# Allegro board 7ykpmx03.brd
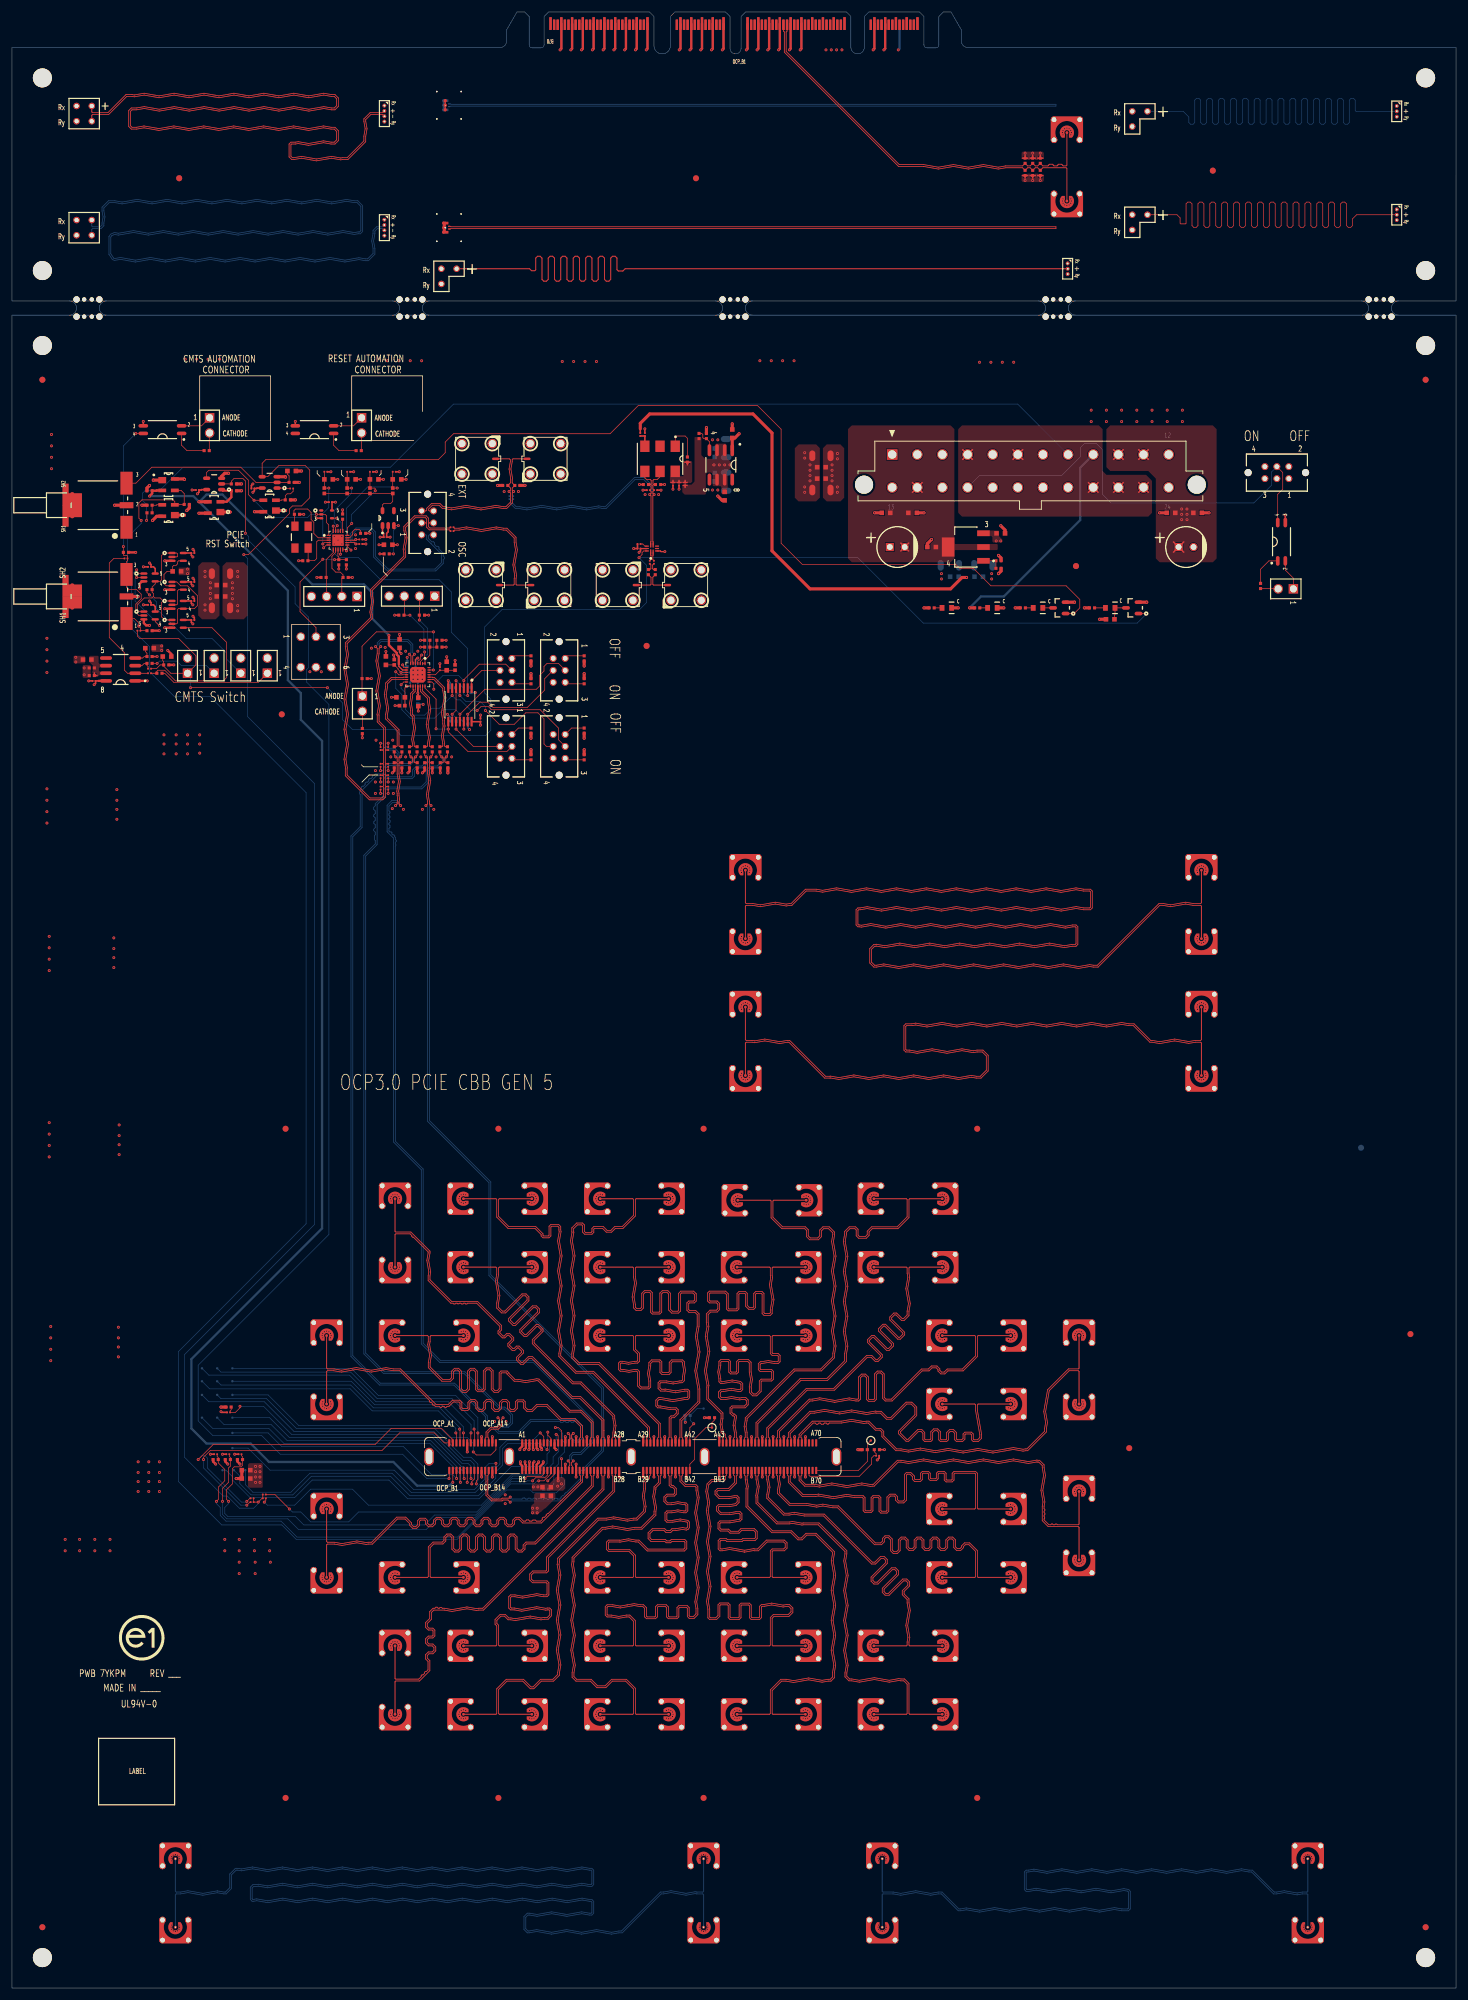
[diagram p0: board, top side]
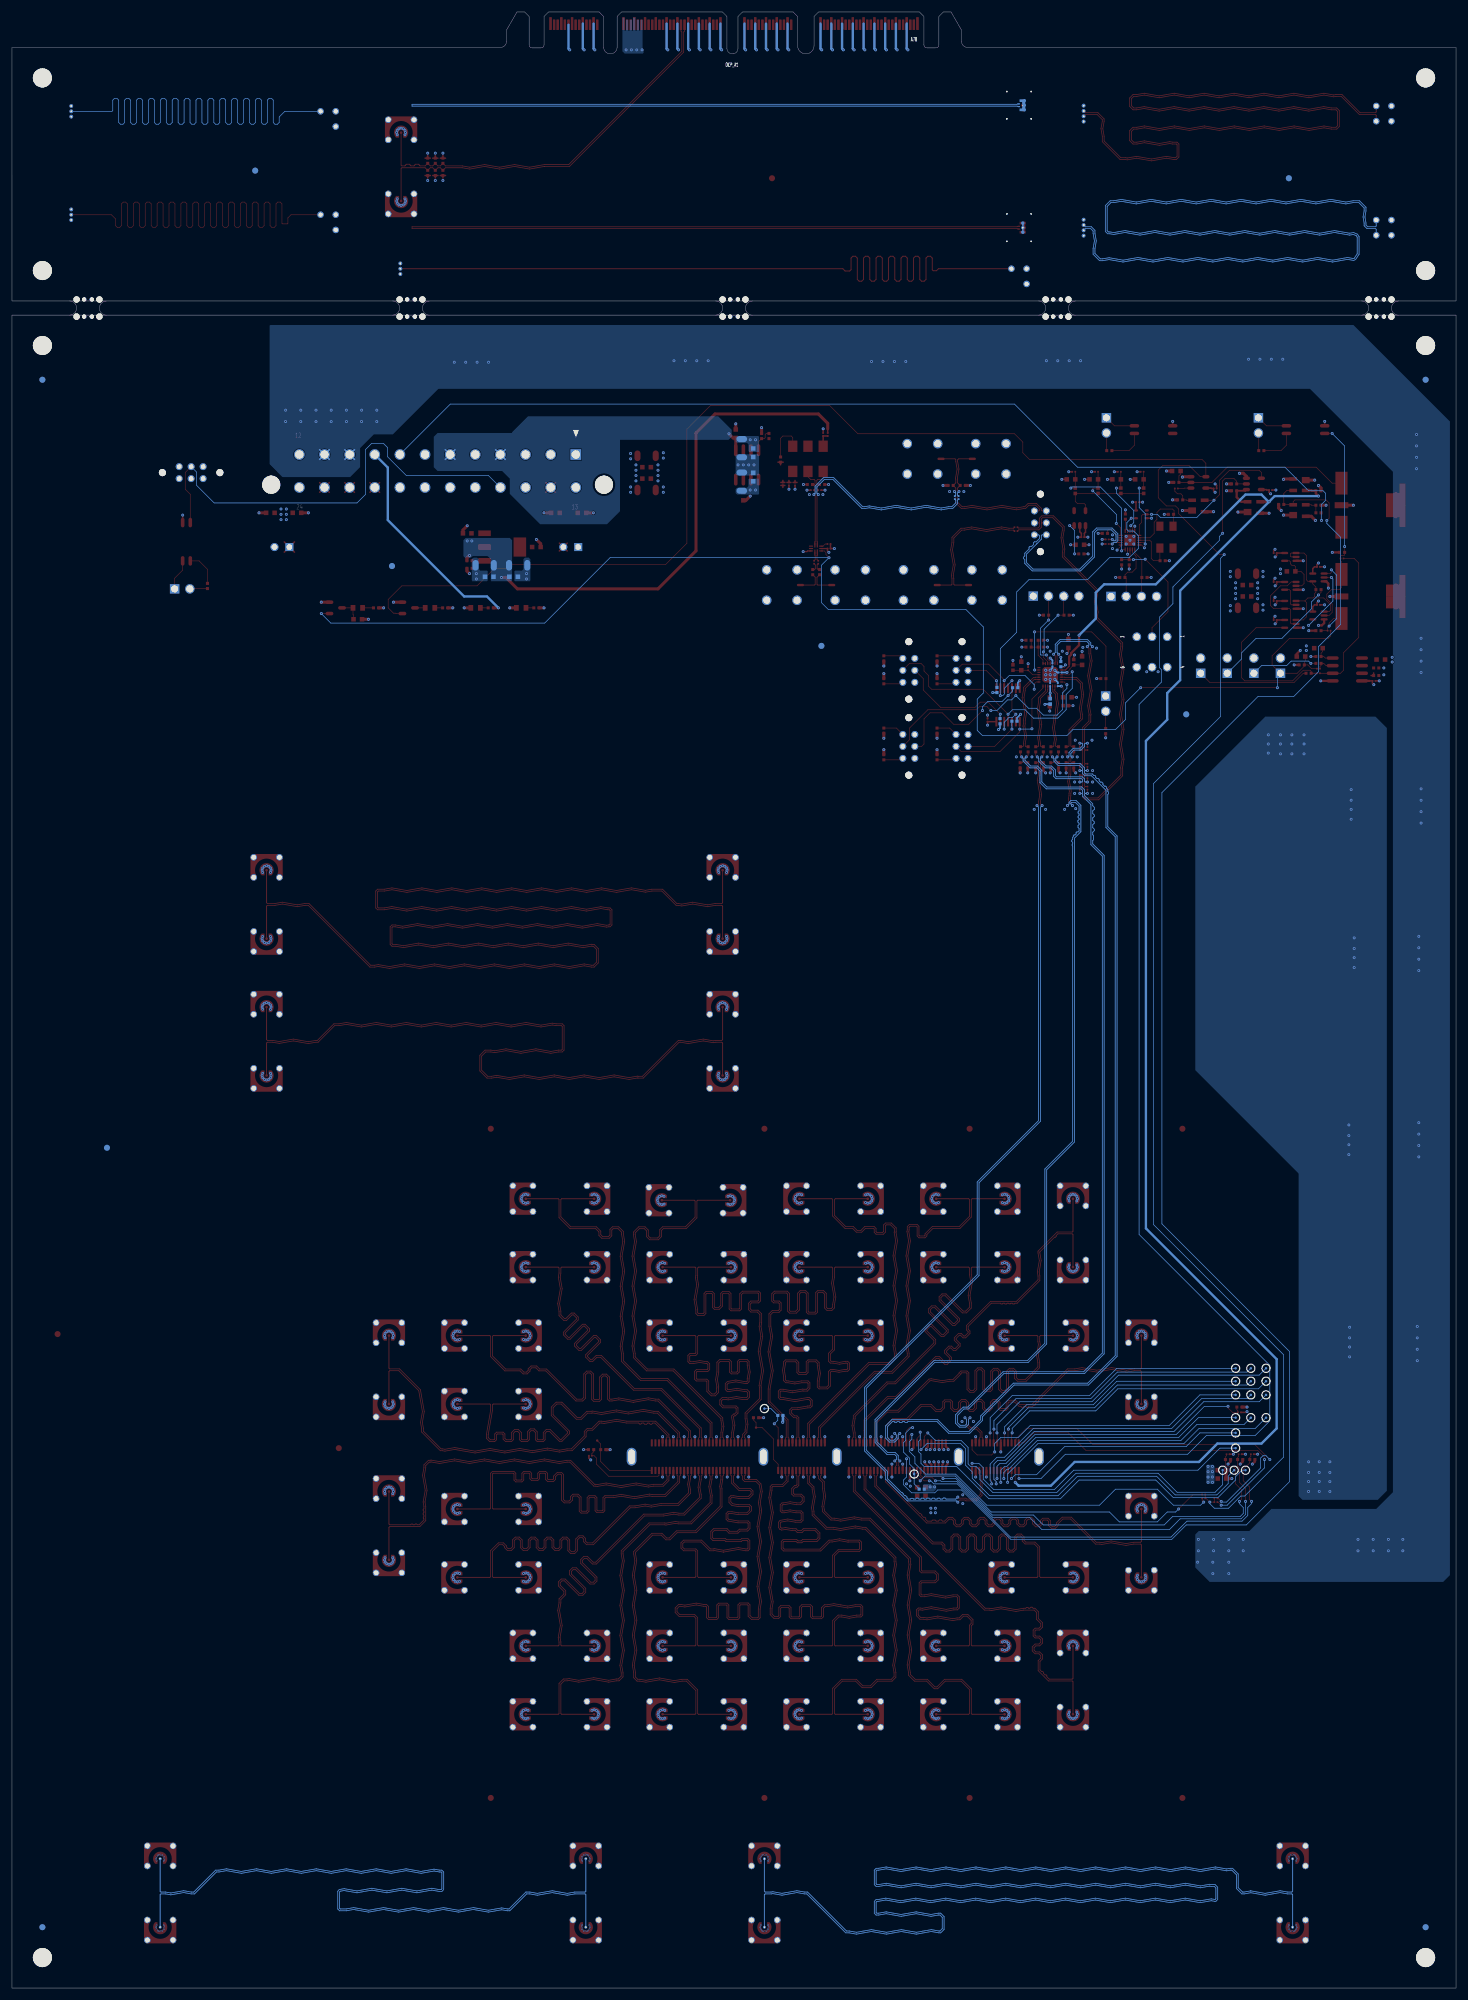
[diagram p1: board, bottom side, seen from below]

Outline 241.3 x 330.03 mm; copper layers: TOP, GND, VCC, GD2, GD3, BOTTOM. Coordinates in mm from the lower left corner of the outline.
Outline path: 9.62,281.75 arc(10.79,280.57) 9.62,279.39 ; 15.77,279.4 arc(14.6,280.58) 15.77,281.76 ; 63.6,281.75 arc(64.77,280.57) 63.6,279.39 ; 69.75,279.4 arc(68.58,280.58) 69.75,281.76 ; 117.57,281.75 arc(118.74,280.57) 117.57,279.39 ; 123.72,279.4 arc(122.55,280.58) 123.72,281.76 ; 171.55,281.75 arc(172.72,280.57) 171.55,279.39 ; 177.7,279.4 arc(176.53,280.58) 177.7,281.76 ; 225.52,281.75 arc(226.69,280.57) 225.52,279.39 ; 231.67,279.4 arc(230.5,280.58) 231.67,281.76 ; 0,324.1 0,281.76 241.3,281.76 241.3,324.1 159.72,324.1 arc(158.96,324.41) 158.65,325.16 158.65,327.03 156.92,330.03 155.64,330.03 154.89,329.28 154.89,324.53 arc(154.74,324.17) 154.39,324.03 152.89,324.03 arc(152.54,324.17) 152.39,324.53 152.39,329.28 151.64,330.03 143.18,330.03 142.43,329.28 142.43,324.15 arc(141.31,323.03) 140.18,324.15 140.18,329.28 139.43,330.03 122.58,330.03 121.83,329.28 121.83,323.95 arc(120.91,323.03) 119.98,323.95 119.98,329.28 119.23,330.03 110.77,330.03 110.02,329.28 110.02,324.4 arc(108.65,323.03) 107.27,324.4 107.27,329.28 106.52,330.03 89.66,330.03 88.91,329.28 88.91,324.53 arc(88.77,324.17) 88.41,324.03 86.91,324.03 arc(86.56,324.17) 86.41,324.53 86.41,329.28 85.66,330.03 84.38,330.03 82.65,327.03 82.65,325.16 arc(82.34,324.41) 81.58,324.1 0,324.1 ; 0,279.4 241.3,279.4 241.3,0 0,0 0,279.4

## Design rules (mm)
constraint set DEFAULT: min track width 0.102
net group ATX_PWR_OK_33: nets ATX_PWR_OK ATX_PWR_OK_33
net group CLK_EXTERNAL_DN: nets CLK_EXTERNAL_DN CLK_OSC1_TO_TRIGGER_DN
net group CLK_EXTERNAL_DP: nets CLK_EXTERNAL_DP CLK_OSC1_TO_TRIGGER_DP
net group CLKBUF_EN_DLY: nets CLKBUF_EN_DLY N16884462
net group N16775589: nets N16775589 N16775601
net group REFCLK0_R: nets REFCLK0_R_DN REFCLK0_R_DP
net group REFCLK1_R: nets REFCLK1_R_DN REFCLK1_R_DP
net group REFCLK2_R: nets REFCLK2_R_DN REFCLK2_R_DP
net group REFCLK3_R: nets REFCLK3_R_DN REFCLK3_R_DP
net group SET2DIL: nets SET2DIL_85_BOT SET2DIL_85_TOP
net group V_5VSTBY: nets N16831963 V_5VSTBY
net group 555_OUT: nets 555_OUT 555_OUT_JP BTN_NC BUS_SEL
net group 555_TRI: nets 555_TRI N16776527 N16776623
net group _UNCONSTRAINED: nets 555_DISCHARGE AUX_PWR_EN BIF0_N BIF1_N BIF2_N CLKBUF_OE0_OFF CLKBUF_OE0_ON CLKBUF_OE1_OFF CLKBUF_OE1_ON CLKBUF_OE2_OFF CLKBUF_OE2_ON CLKBUF_OE3_OFF CLKBUF_OE3_ON NCSI_ARBIN NCSI_ARBOUT NCSI_CRS_DV NCSI_TXEN SCAN_DATA_IN SCAN_DATA_OUT SCAN_LD_N SLOT_ID
net group CLK_SE: nets 555_RST_N CLK_NCSI NCSI_RXD0 NCSI_RXD1 NCSI_TXD0 NCSI_TXD1 NIC_PWR_GOOD SCAN_CLK SMB_CLK SMB_RST_N SMB_SDA WAKE_N
net group CLK_TRIG_SIGNAL_C_DN: nets CLK_TRIG_SIGNAL_C_DN CLK_TRIG_SIGNAL_DN CLK_TRIG_SIGNAL_R_DN
net group CLK_TRIG_SIGNAL_C_DP: nets CLK_TRIG_SIGNAL_C_DP CLK_TRIG_SIGNAL_DP CLK_TRIG_SIGNAL_R_DP
net group COUPONS: nets Z_85D_BOT_DN Z_85D_BOT_DP Z_85D_TOP_DN Z_85D_TOP_DP
net group GND: nets GND_SIGNAL
net group GND_OSC1: nets 337_ADJ GND_OSC1 V_1P65_NEG
net group PE_SIGNALS: nets PE_CAL_CPU_OCP_0_DN PE_CAL_CPU_OCP_0_DP PE_CPU_OCP_0_DN PE_CPU_OCP_0_DP PE_CPU_OCP_1_DN PE_CPU_OCP_1_DP PE_CPU_OCP_2_DN PE_CPU_OCP_2_DP PE_CPU_OCP_3_DN PE_CPU_OCP_3_DP PE_CPU_OCP_4_DN PE_CPU_OCP_4_DP PE_CPU_OCP_5_DN PE_CPU_OCP_5_DP PE_CPU_OCP_6_DN PE_CPU_OCP_6_DP PE_CPU_OCP_7_DN PE_CPU_OCP_7_DP PE_CPU_OCP_8_DN PE_CPU_OCP_8_DP PE_CPU_OCP_9_DN PE_CPU_OCP_9_DP PE_CPU_OCP_10_DN PE_CPU_OCP_10_DP PE_CPU_OCP_11_DN PE_CPU_OCP_11_DP PE_CPU_OCP_12_DN PE_CPU_OCP_12_DP PE_CPU_OCP_13_DN PE_CPU_OCP_13_DP PE_CPU_OCP_14_DN PE_CPU_OCP_14_DP PE_CPU_OCP_15_DN PE_CPU_OCP_15_DP PE_OCP_CPU_0_DN PE_OCP_CPU_0_DP PE_OCP_CPU_1_DN PE_OCP_CPU_1_DP PE_OCP_CPU_2_DN PE_OCP_CPU_2_DP PE_OCP_CPU_3_DN PE_OCP_CPU_3_DP PE_OCP_CPU_4_DN PE_OCP_CPU_4_DP PE_OCP_CPU_5_DN PE_OCP_CPU_5_DP PE_OCP_CPU_6_DN PE_OCP_CPU_6_DP PE_OCP_CPU_7_DN PE_OCP_CPU_7_DP PE_OCP_CPU_8_DN PE_OCP_CPU_8_DP PE_OCP_CPU_9_DN PE_OCP_CPU_9_DP PE_OCP_CPU_10_DN PE_OCP_CPU_10_DP PE_OCP_CPU_11_DN PE_OCP_CPU_11_DP PE_OCP_CPU_12_DN PE_OCP_CPU_12_DP PE_OCP_CPU_13_DN PE_OCP_CPU_13_DP PE_OCP_CPU_14_DN PE_OCP_CPU_14_DP PE_OCP_CPU_15_DN PE_OCP_CPU_15_DP
net group PERST1_N: nets PCIE_RST_BTN_N PERST0_N PERST1_N PERST2_N PERST3_N
net group REFCLK1_DN: nets CLK_BASE_TO_DEVICE_R_DN
net group REFCLK1_DP: nets CLK_BASE_TO_DEVICE_R_DP
net group V_12V: nets N16833101 N16833103 V_12V
net group VCC_OSC1: nets 317_ADJ N16798679 V_1P65 VCC_OSC1

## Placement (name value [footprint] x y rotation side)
C1  10uF  [C0603]  39.12 86.49 0 top
C2  2.2uF  [C0603]  39.12 85.09 0 top
C3  10uF  [C0603]  88.65 82.93 90 top
C4  2.2uF  [C0603]  90.04 82.93 90 top
C5  0.1uF  [C0201]  13.72 218.31 180 top
C6  0.1uF  [C0201]  22.99 237.36 0 top
C7  0.1uF  [C0201]  30.23 231.65 180 top
C8  0.1uF  [C0201]  30.23 228.47 180 top
C9  0.1uF  [C0201]  30.23 239.65 180 top
C10  10uF  [C0603]  12.57 221.87 180 top
C11  10uF  [C0603]  22.99 223.77 0 top
C12  0.1uF  [C0201]  22.99 231.01 0 top
C13  0.1uF  [C0201]  30.23 234.82 180 top
C14  10uF  [C0603]  27.56 236.6 0 top
C15  1uF  [C0603]  25.91 222.38 0 top
C16  0.1uF  [C0201]  104.77 240.41 180 top
C17  0.1uF  [C0201]  106.58 238.12 90 top
C18  0.1uF  [C0201]  107.26 238.12 90 top
C19  47uF  [C1206]  34.92 236.22 180 top
C20  47uF  [C1206]  34.92 230.51 180 top
C21  10uF  [C0603]  34.92 232.41 0 top
C22  2.2uF  [C0603]  34.92 234.32 180 top
C23  0.1uF  [C0201]  111.47 251.21 270 top
C25  0.056uF  [C0402]  84.45 250.95 180 top
C26  0.056uF  [C0402]  82.42 250.95 0 top
C36  1uF  [C0603]  120.36 259.59 270 top
C37  1uF  [C0603]  119.09 249.17 90 top
C38  47uF  [C1206]  119.34 257.18 270 bottom
C39  47uF  [C1206]  119.34 251.59 90 bottom
C40  10uF  [C0603]  117.44 256.41 90 bottom
C41  2.2uF  [C0603]  117.44 252.35 90 bottom
C42  1uF  [C0603]  153.67 240.67 0 top
C43  1uF  [C0603]  165.23 242.95 180 top
C44  47uF  [C1206]  156.72 237.62 0 bottom
C45  47uF  [C1206]  162.31 237.62 180 bottom
C46  10uF  [C0603]  157.48 235.71 180 bottom
C47  2.2uF  [C0603]  161.54 235.71 180 bottom
C48  10uF  [C0603]  183.52 228.6 0 top
C49  47uF  [C1206]  135.26 255.91 0 top
C50  47uF  [C1206]  135.26 250.19 0 top
C51  10uF  [C0603]  135.26 254 180 top
C52  2.2uF  [C0603]  135.26 252.09 0 top
C53  100uF  [2RAD268D236H098P]  194.95 240.67 0 top
C54  10uF  [C0603]  193.68 246.38 180 top
C55  2.2uF  [C0603]  198.12 246.38 180 top
C56  100uF  [2RAD268D236H098P]  146.69 240.67 0 top
C57  10uF  [C0603]  146.05 246.38 180 top
C58  2.2uF  [C0603]  150.5 246.38 180 top
C59  0.1uF  [C0201]  30.99 250.19 0 top
C60  1uF  [C0603]  46.74 253.37 180 top
C125  0.056uF  [C0402]  170.56 305.18 270 top
C126  0.056uF  [C0402]  169.29 305.18 270 top
C127  0.056uF  [C0402]  170.56 303.15 90 top
C128  0.056uF  [C0402]  169.29 303.15 90 top
C129  0.1uF  [C0201]  40.26 250.44 0 top
C130  0.1uF  [C0201]  62.36 242.32 0 top
C131  1uF  [C0603]  62.86 241.05 0 top
C132  1uF  [C0603]  52.91 251.97 0 top
C133  0.1uF  [C0201]  52.45 253.24 0 top
C134  1uF  [C0603]  64.34 251.97 0 top
C135  0.1uF  [C0201]  63.88 253.24 0 top
C136  1uF  [C0603]  60.53 251.97 0 top
C137  0.1uF  [C0201]  60.07 253.24 0 top
C138  1uF  [C0603]  56.72 251.97 0 top
C139  0.1uF  [C0201]  56.26 253.24 0 top
C140  22pF  [C0402]  47.62 246.13 180 top
C141  22pF  [C0402]  49.02 238.38 0 top
C142  0.1uF  [C0201]  66.17 219.71 0 bottom
C143  1uF  [C0603]  62.48 221.69 90 top
C144  0.1uF  [C0201]  66.55 217.68 90 bottom
C145  1uF  [C0603]  64.95 215.57 180 top
C146  0.1uF  [C0201]  67.44 220.98 270 bottom
C147  1uF  [C0603]  64.77 224.54 90 top
C148  0.1uF  [C0201]  67.82 217.68 90 bottom
C149  1uF  [C0603]  67.89 214.81 270 top
C150  0.1uF  [C0201]  71.5 220.34 90 top
C151  1uF  [C0603]  72.64 220.8 90 top
C152  0.1uF  [C0201]  78.28 211.76 90 top
C153  0.1uF  [C0201]  53.21 248.16 0 top
DS1  PS2801  [SOIC127P700X230_4N]  25.15 260.27 180 top
DS2  PS2801  [SOIC127P700X230_4N]  212.14 241.55 90 top
DS3  PS2801  [SOIC127P700X230_4N]  50.55 260.27 180 top
DS_3P3V  APH1608-TD47  [LEDC1608X65N]  156.21 230.51 0 top
DS_5VSTBY  APH1608-TD47  [LEDC1608X65N]  163.83 230.51 0 top
DS_RST  APH1608-TD47  [LEDC1608X65N]  171.45 230.51 0 top
DS_TRIG  APH1608-TD47  [LEDC1608X65N]  183.52 230.51 0 top
J_S2D_BOT  SET2DIL,COUPON  [TP3_PPROBEB]  72.39 314.45 0 bottom
J_S2D_TOP  SET2DIL,COUPON  [TP3_PPROBEB]  72.39 294 0 top
L3  600  [FB1005X55N]  52.2 250.06 90 top
L4  600  [FB1005X55N]  63.63 250.06 90 top
L5  600  [FB1005X55N]  59.82 250.06 90 top
L6  600  [FB1005X55N]  56.01 250.06 90 top
L7  600  [FB1005X55N]  63.88 221.43 270 top
L8  600  [FB1005X55N]  65.2 214.17 0 top
L9  600  [FB1005X55N]  67.82 214.88 90 bottom
L10  600  [FB1005X55N]  74.04 220.54 270 top
LBL1  2d_label500x437  [2D_LABEL500X437]  14.48 30.61 0 top
NOREF  -  [unnamed]  5.08 319.02 0 top
NOREF#2  -  [#2]  97.16 330.83 90 top
NOREF#3  -  [#2]  236.22 5.08 0 top
NOREF#4  -  [#2]  241.3 0 0 top
NOREF#5  -  [unnamed#3]  66.67 279.15 0 top
NOREF#6  -  [unnamed]  236.22 268.6 0 top
NOREF#7  -  [#2]  0 0 0 top
NOREF#8  -  [#2]  85.66 330.03 0 top
NOREF#9  -  [#2]  5.08 5.08 0 top
NOREF#10  -  [unnamed]  186.69 90.17 180 top
NOREF#11  -  [#2]  5.08 5.08 0 top
NOREF#12  -  [unnamed]  5.08 10.16 0 top
NOREF#13  -  [unnamed]  236.22 286.84 0 top
NOREF#14  -  [unnamed]  27.94 302.26 0 top
NOREF#15  -  [#2]  5.08 274.32 0 top
NOREF#16  -  [unnamed#3]  12.7 279.15 0 top
NOREF#17  -  [unnamed]  200.66 303.53 0 top
NOREF#18  -  [unnamed]  115.57 31.75 0 top
NOREF#19  -  [#2]  0 279.4 0 top
NOREF#20  -  [#2]  328.19 329.97 0 top
NOREF#21  -  [unnamed#3]  228.6 282.02 0 top
NOREF#22  -  [unnamed#3]  174.62 282.02 0 top
NOREF#23  -  [#2]  36.83 492.76 0 top
NOREF#24  -  [#2]  5.08 319.02 0 top
NOREF#25  -  [unnamed]  161.29 143.51 180 top
NOREF#26  -  [unnamed]  233.68 109.22 0 top
NOREF#27  -  [#2]  21.68 58.5 0 top
NOREF#28  -  [unnamed]  5.08 274.32 0 top
NOREF#29  -  [unnamed#3]  12.7 282.02 0 top
NOREF#30  -  [unnamed]  45.72 143.51 180 top
NOREF#31  -  [#2]  241.3 0 0 top
NOREF#32  -  [unnamed#3]  120.65 279.15 0 top
NOREF#33  -  [#2]  0 324.1 0 top
NOREF#34  -  [unnamed]  5.08 286.84 0 top
NOREF#35  -  [unnamed#3]  120.65 282.02 0 top
NOREF#36  -  [#2]  0 0 0 top
NOREF#37  -  [unnamed]  236.22 10.16 0 top
NOREF#38  -  [unnamed]  236.22 5.08 0 top
NOREF#39  -  [unnamed]  114.3 302.26 0 top
NOREF#40  -  [unnamed#3]  66.67 282.02 0 top
NOREF#41  -  [unnamed]  161.29 31.75 180 top
NOREF#42  -  [unnamed]  177.8 237.49 0 top
NOREF#43  -  [unnamed]  236.22 319.02 0 top
NOREF#44  -  [#2]  5.08 286.84 0 top
NOREF#45  -  [unnamed]  45.72 31.75 180 top
NOREF#46  -  [unnamed#3]  228.6 279.15 0 top
NOREF#47  -  [unnamed]  81.28 31.75 180 top
NOREF#48  -  [unnamed]  115.57 143.51 180 top
NOREF#49  -  [#2]  0 281.76 0 top
NOREF#50  -  [unnamed]  81.28 143.51 180 top
NOREF#51  -  [unnamed]  106.05 224.16 0 top
NOREF#52  -  [unnamed]  5.08 5.08 0 top
NOREF#53  -  [#2]  236.22 5.08 0 top
NOREF#54  -  [unnamed#3]  174.62 279.15 0 top
NOREF#55  -  [unnamed]  5.08 268.6 0 top
NOREF#56  -  [unnamed]  45.09 212.73 0 top
NOREF#57  -  [unnamed]  236.22 274.32 0 top
NOREF#58  -  [unnamed]  177.8 237.49 180 bottom
NOREF#59  -  [unnamed]  225.43 140.34 180 bottom
NOREF#60  -  [unnamed]  200.66 303.53 180 bottom
NOREF#61  -  [unnamed]  236.22 10.16 180 bottom
NOREF#62  -  [unnamed]  236.22 268.6 180 bottom
NOREF#63  -  [unnamed]  5.08 268.6 180 bottom
NOREF#64  -  [unnamed]  27.94 302.26 180 bottom
NOREF#65  -  [unnamed]  106.05 224.16 180 bottom
NOREF#66  -  [unnamed]  5.08 10.16 180 bottom
NOREF#67  -  [unnamed]  45.09 212.73 180 bottom
P1  2X1,VERT,HDR  [BERG1X2]  42.67 219.58 180 top
P2  2X1,VERT,HDR  [BERG1X2]  38.23 219.58 180 top
P3  2X1,VERT,HDR  [BERG1X2]  33.78 219.58 180 top
P4  2X1,VERT,HDR  [BERG1X2]  29.34 219.58 180 top
P6  1X4,VERT,HDR  [BERG1X4]  57.66 232.41 270 top
P7  1X4,VERT,HDR  [BERG1X4]  70.64 232.46 270 top
P8  2X1,VERT,HDR  [BERG1X2]  33.02 262.25 0 top
P9  2X1,VERT,HDR  [BERG1X2]  214.12 233.68 270 top
P10  2X1,VERT,HDR  [BERG1X2]  58.42 262.25 0 top
P_ATX  2x12,ATX PWR  [CON_HDR_2X12_ST_TH_PWR]  147.08 256.12 0 top
P_CAL_CPU_OCP_0_N  COAX,FEMALE  [96_MMPX-50-0-3_L1_CASEA]  176.28 309.88 270 top
P_CAL_CPU_OCP_0_P  COAX,FEMALE  [96_MMPX-50-0-3_L1_CASEA]  176.28 298.45 90 top
P_CMTS_N  JACK,STRAIGHT PLUG PCB  [CON_SMP_PLUG_STF]  112.65 234.32 90 top
P_CMTS_P  JACK,STRAIGHT PLUG PCB  [CON_SMP_PLUG_STF]  101.22 234.32 270 top
P_CPU_OCP_0_N1  COAX,FEMALE  [96_MMPX-50-0-3_L1_CASEA]  52.58 80.01 270 top
P_CPU_OCP_0_P1  COAX,FEMALE  [96_MMPX-50-0-3_L1_CASEA]  52.58 68.58 90 top
P_CPU_OCP_1_N1  COAX,FEMALE  [96_MMPX-50-0-3_L1_CASEA]  64.01 68.58 0 top
P_CPU_OCP_1_P1  COAX,FEMALE  [96_MMPX-50-0-3_L1_CASEA]  75.44 68.58 180 top
P_CPU_OCP_2_N1  COAX,FEMALE  [96_MMPX-50-0-3_L1_CASEA]  64.01 57.15 270 top
P_CPU_OCP_2_P1  COAX,FEMALE  [96_MMPX-50-0-3_L1_CASEA]  64.01 45.72 90 top
P_CPU_OCP_3_N1  COAX,FEMALE  [96_MMPX-50-0-3_L1_CASEA]  75.44 57.15 0 top
P_CPU_OCP_3_P1  COAX,FEMALE  [96_MMPX-50-0-3_L1_CASEA]  86.87 57.15 180 top
P_CPU_OCP_4_N  COAX,FEMALE  [96_MMPX-50-0-3_L1_CASEA]  75.44 45.72 0 top
P_CPU_OCP_4_P  COAX,FEMALE  [96_MMPX-50-0-3_L1_CASEA]  86.87 45.72 180 top
P_CPU_OCP_5_N  COAX,FEMALE  [96_MMPX-50-0-3_L1_CASEA]  98.3 45.72 0 top
P_CPU_OCP_5_P  COAX,FEMALE  [96_MMPX-50-0-3_L1_CASEA]  109.73 45.72 180 top
P_CPU_OCP_6_N  COAX,FEMALE  [96_MMPX-50-0-3_L1_CASEA]  98.3 68.58 0 top
P_CPU_OCP_6_P  COAX,FEMALE  [96_MMPX-50-0-3_L1_CASEA]  109.73 68.58 180 top
P_CPU_OCP_7_N  COAX,FEMALE  [96_MMPX-50-0-3_L1_CASEA]  98.3 57.15 0 top
P_CPU_OCP_7_P  COAX,FEMALE  [96_MMPX-50-0-3_L1_CASEA]  109.73 57.15 180 top
P_CPU_OCP_8_N  COAX,FEMALE  [96_MMPX-50-0-3_L1_CASEA]  121.16 57.15 0 top
P_CPU_OCP_8_P  COAX,FEMALE  [96_MMPX-50-0-3_L1_CASEA]  132.59 57.15 180 top
P_CPU_OCP_9_N  COAX,FEMALE  [96_MMPX-50-0-3_L1_CASEA]  121.16 68.58 0 top
P_CPU_OCP_9_P  COAX,FEMALE  [96_MMPX-50-0-3_L1_CASEA]  132.59 68.58 180 top
P_CPU_OCP_10_N  COAX,FEMALE  [96_MMPX-50-0-3_L1_CASEA]  121.16 45.72 0 top
P_CPU_OCP_10_P  COAX,FEMALE  [96_MMPX-50-0-3_L1_CASEA]  132.59 45.72 180 top
P_CPU_OCP_11_N  COAX,FEMALE  [96_MMPX-50-0-3_L1_CASEA]  144.02 45.72 0 top
P_CPU_OCP_11_P  COAX,FEMALE  [96_MMPX-50-0-3_L1_CASEA]  155.45 45.72 180 top
P_CPU_OCP_12_N  COAX,FEMALE  [96_MMPX-50-0-3_L1_CASEA]  144.02 57.15 0 top
P_CPU_OCP_12_P  COAX,FEMALE  [96_MMPX-50-0-3_L1_CASEA]  155.45 57.15 180 top
P_CPU_OCP_13_N  COAX,FEMALE  [96_MMPX-50-0-3_L1_CASEA]  155.45 68.58 0 top
P_CPU_OCP_13_P  COAX,FEMALE  [96_MMPX-50-0-3_L1_CASEA]  166.88 68.58 180 top
P_CPU_OCP_14_N  COAX,FEMALE  [96_MMPX-50-0-3_L1_CASEA]  155.45 80.01 0 top
P_CPU_OCP_14_P  COAX,FEMALE  [96_MMPX-50-0-3_L1_CASEA]  166.88 80.01 180 top
P_CPU_OCP_15_N  COAX,FEMALE  [96_MMPX-50-0-3_L1_CASEA]  178.31 71.5 90 top
P_CPU_OCP_15_P  COAX,FEMALE  [96_MMPX-50-0-3_L1_CASEA]  178.31 82.93 270 top
P_EXT_CLK_N  JACK,STRAIGHT PLUG PCB  [CON_SMP_PLUG_STF]  89.15 255.4 90 top
P_EXT_CLK_P  JACK,STRAIGHT PLUG PCB  [CON_SMP_PLUG_STF]  77.72 255.4 270 top
P_NOISEINJ_N  JACK,STRAIGHT PLUG PCB  [CON_SMP_PLUG_STF]  89.79 234.32 90 top
P_NOISEINJ_P  JACK,STRAIGHT PLUG PCB  [CON_SMP_PLUG_STF]  78.36 234.32 270 top
P_OCP  2X84 PIN,0.6MM  [C2X84STF_MCE_0P60_5MH_2PG]  71.25 87 0 top
P_OCP_CPU_0_N1  COAX,FEMALE  [96_MMPX-50-0-3_L1_CASEA]  52.58 97.54 90 top
P_OCP_CPU_0_P1  COAX,FEMALE  [96_MMPX-50-0-3_L1_CASEA]  52.58 108.97 270 top
P_OCP_CPU_1_N1  COAX,FEMALE  [96_MMPX-50-0-3_L1_CASEA]  64.01 108.97 0 top
P_OCP_CPU_1_P1  COAX,FEMALE  [96_MMPX-50-0-3_L1_CASEA]  75.44 108.97 180 top
P_OCP_CPU_2_N1  COAX,FEMALE  [96_MMPX-50-0-3_L1_CASEA]  64.01 120.4 90 top
P_OCP_CPU_2_P1  COAX,FEMALE  [96_MMPX-50-0-3_L1_CASEA]  64.01 131.83 270 top
P_OCP_CPU_3_N1  COAX,FEMALE  [96_MMPX-50-0-3_L1_CASEA]  75.44 120.4 0 top
P_OCP_CPU_3_P1  COAX,FEMALE  [96_MMPX-50-0-3_L1_CASEA]  86.87 120.4 180 top
P_OCP_CPU_4_N  COAX,FEMALE  [96_MMPX-50-0-3_L1_CASEA]  75.44 131.83 0 top
P_OCP_CPU_4_P4  COAX,FEMALE  [96_MMPX-50-0-3_L1_CASEA]  86.87 131.83 180 top
P_OCP_CPU_5_N  COAX,FEMALE  [96_MMPX-50-0-3_L1_CASEA]  98.3 131.83 0 top
P_OCP_CPU_5_P  COAX,FEMALE  [96_MMPX-50-0-3_L1_CASEA]  109.73 131.83 180 top
P_OCP_CPU_6_N  COAX,FEMALE  [96_MMPX-50-0-3_L1_CASEA]  98.3 108.97 0 top
P_OCP_CPU_6_P  COAX,FEMALE  [96_MMPX-50-0-3_L1_CASEA]  109.73 108.97 180 top
P_OCP_CPU_7_N  COAX,FEMALE  [96_MMPX-50-0-3_L1_CASEA]  98.3 120.4 0 top
P_OCP_CPU_7_P  COAX,FEMALE  [96_MMPX-50-0-3_L1_CASEA]  109.73 120.4 180 top
P_OCP_CPU_8_N  COAX,FEMALE  [96_MMPX-50-0-3_L1_CASEA]  121.16 120.4 0 top
P_OCP_CPU_8_P  COAX,FEMALE  [96_MMPX-50-0-3_L1_CASEA]  132.59 120.4 180 top
P_OCP_CPU_9_N  COAX,FEMALE  [96_MMPX-50-0-3_L1_CASEA]  121.16 108.97 0 top
P_OCP_CPU_9_P  COAX,FEMALE  [96_MMPX-50-0-3_L1_CASEA]  132.59 108.97 180 top
P_OCP_CPU_10_N  COAX,FEMALE  [96_MMPX-50-0-3_L1_CASEA]  121.28 131.57 0 top
P_OCP_CPU_10_P  COAX,FEMALE  [96_MMPX-50-0-3_L1_CASEA]  132.72 131.57 180 top
P_OCP_CPU_11_N  COAX,FEMALE  [96_MMPX-50-0-3_L1_CASEA]  144.02 131.83 0 top
P_OCP_CPU_11_P  COAX,FEMALE  [96_MMPX-50-0-3_L1_CASEA]  155.45 131.83 180 top
P_OCP_CPU_12_N  COAX,FEMALE  [96_MMPX-50-0-3_L1_CASEA]  144.02 120.4 0 top
P_OCP_CPU_12_P  COAX,FEMALE  [96_MMPX-50-0-3_L1_CASEA]  155.45 120.4 180 top
P_OCP_CPU_13_N  COAX,FEMALE  [96_MMPX-50-0-3_L1_CASEA]  155.45 108.97 0 top
P_OCP_CPU_13_P  COAX,FEMALE  [96_MMPX-50-0-3_L1_CASEA]  166.88 108.97 180 top
P_OCP_CPU_14_N  COAX,FEMALE  [96_MMPX-50-0-3_L1_CASEA]  155.45 97.54 0 top
P_OCP_CPU_14_P  COAX,FEMALE  [96_MMPX-50-0-3_L1_CASEA]  166.88 97.54 180 top
P_OCP_CPU_15_N  COAX,FEMALE  [96_MMPX-50-0-3_L1_CASEA]  178.31 108.97 270 top
P_OCP_CPU_15_P  COAX,FEMALE  [96_MMPX-50-0-3_L1_CASEA]  178.31 97.54 90 top
P_OCPEDGE  CON,EC,168,.6MM,S,G,ST  [CON_AMP_EDGE_ME101681340131X]  89.99 328.09 0 top
P_SLEWRATE_SEL  2X1,VERT,HDR  [BERG1X2]  58.55 215.77 0 top
P_SMA_BOT_5IN_DN_1  COAX,FEMALE  [96_MMPX-50-0-3_L1_CASEA#2]  145.42 10.16 90 top
P_SMA_BOT_5IN_DN_2  COAX,FEMALE  [96_MMPX-50-0-3_L1_CASEA#2]  216.54 10.16 90 top
P_SMA_BOT_5IN_DP_1  COAX,FEMALE  [96_MMPX-50-0-3_L1_CASEA#2]  145.42 21.59 270 top
P_SMA_BOT_5IN_DP_2  COAX,FEMALE  [96_MMPX-50-0-3_L1_CASEA#2]  216.54 21.59 270 top
P_SMA_BOT_10IN_DN_1  COAX,FEMALE  [96_MMPX-50-0-3_L1_CASEA#2]  27.3 10.16 90 top
P_SMA_BOT_10IN_DN_2  COAX,FEMALE  [96_MMPX-50-0-3_L1_CASEA#2]  115.57 10.16 90 top
P_SMA_BOT_10IN_DP_1  COAX,FEMALE  [96_MMPX-50-0-3_L1_CASEA#2]  27.3 21.59 270 top
P_SMA_BOT_10IN_DP_2  COAX,FEMALE  [96_MMPX-50-0-3_L1_CASEA#2]  115.57 21.59 270 top
P_SMA_TOP_5IN_DN_1  COAX,FEMALE  [96_MMPX-50-0-3_L1_CASEA]  122.55 152.4 90 top
P_SMA_TOP_5IN_DN_2  COAX,FEMALE  [96_MMPX-50-0-3_L1_CASEA]  198.76 152.4 90 top
P_SMA_TOP_5IN_DP_1  COAX,FEMALE  [96_MMPX-50-0-3_L1_CASEA]  122.55 163.83 270 top
P_SMA_TOP_5IN_DP_2  COAX,FEMALE  [96_MMPX-50-0-3_L1_CASEA]  198.76 163.83 270 top
P_SMA_TOP_10IN_DN_1  COAX,FEMALE  [96_MMPX-50-0-3_L1_CASEA]  122.55 175.26 90 top
P_SMA_TOP_10IN_DN_2  COAX,FEMALE  [96_MMPX-50-0-3_L1_CASEA]  198.76 175.26 90 top
P_SMA_TOP_10IN_DP_1  COAX,FEMALE  [96_MMPX-50-0-3_L1_CASEA]  122.55 186.69 270 top
P_SMA_TOP_10IN_DP_2  COAX,FEMALE  [96_MMPX-50-0-3_L1_CASEA]  198.76 186.69 270 top
Q1  2N7002K  [SOT95P237X117_3N]  175.01 230.51 180 top
Q2  2N7002K  [SOT95P237X117_3N]  187.2 230.51 180 top
R1  1K  [R0402]  116.97 95.25 180 top
R2  0  [R0201]  40.13 81.15 0 top
R3  1K  [R0402]  112.9 95.63 180 bottom
R4  1K  [R0402]  89.28 83.31 180 bottom
R5  1K  [R0402]  34.04 88.27 0 top
R6  0  [R0201]  36.07 89.15 0 top
R7  0  [R0201]  34.04 89.15 0 top
R8  0  [R0201]  40.13 81.79 0 top
R9  1K  [R0402]  36.2 97.03 180 top
R10  1K  [R0402]  142.49 89.92 180 top
R11  0  [R0201]  36.2 96.14 0 top
R12  1K  [R0402]  38.1 88.27 0 top
R13  1K  [R0402]  36.07 88.27 0 top
R14  0  [R0201]  38.1 89.15 0 top
R15  0  [R0201]  42.16 82.42 0 top
R16  0  [R0201]  42.16 81.79 180 top
R17  1K  [R0402]  144.53 89.92 180 top
R18  0  [R0201]  144.65 88.9 180 top
R19  0  [R0201]  19.05 238.76 180 top
R20  10K  [R0402]  22.99 226.7 0 top
R21  1K  [R0402]  22.99 233.55 0 top
R22  1K  [R0402]  24.64 219.58 180 top
R23  1K  [R0402]  13.34 220.47 0 top
R24  10K  [R0402]  13.34 219.2 180 top
R25  0  [R0201]  22.99 219.58 180 top
R26  1K  [R0402]  22.99 222.38 180 top
R27  1K  [R0402]  22.99 221.23 0 top
R28  10K  [R0402]  19.05 239.78 0 top
R29  0  [R0201]  22.99 220.34 180 top
R30  10K  [R0402]  25.78 220.98 0 top
R31  0  [R0201]  21.21 226.7 180 top
R32  24.3  [R0402]  106.35 236.47 270 top
R33  1K  [R0201]  104.77 241.17 0 top
R34  24.3  [R0402]  107.49 236.47 270 top
R35  0  [R0201]  112.48 251.21 270 top
R36  0  [R0201]  110.45 251.21 270 top
R37  1K  [R0402]  112.86 255.27 90 top
R38  0  [R0201]  107.56 250.16 0 top
R39  0  [R0201]  106.34 250.16 180 top
R43  0  [R0201]  58.29 241.17 0 top
R44  0  [R0201]  58.29 241.94 0 top
R45  0  [R0201]  104.99 259.46 90 top
R47  0  [R0201]  105.75 259.46 270 top
R48  45.3  [R0402]  107.96 251.1 180 top
R49  45.3  [R0402]  105.93 251.1 0 top
R53  0  [R0201]  83.76 248.92 270 bottom
R54  0  [R0201]  83.12 248.92 270 bottom
R55  0  [R0201]  73.53 243.97 180 top
R56  0  [R0201]  73.53 243.33 180 top
R70  33.2  [R0402]  72.77 206.88 270 top
R72  43.2  [R0402]  63.88 204.22 90 top
R73  43.2  [R0402]  68.96 204.22 90 top
R78  43.2  [R0402]  65.15 204.22 90 top
R79  43.2  [R0402]  70.23 204.22 90 top
R81  43.2  [R0402]  66.42 204.22 90 top
R82  43.2  [R0402]  71.56 204.22 90 top
R83  43.2  [R0402]  67.72 204.22 90 top
R84  43.2  [R0402]  72.83 204.22 90 top
R86  4.7K  [R0402]  86.73 222.06 270 top
R87  4.7K  [R0402]  95.62 210 270 top
R88  4.7K  [R0402]  86.73 210 270 top
R89  4.7K  [R0402]  95.62 222.06 270 top
R90  4.7K  [R0402]  86.73 218.25 270 top
R91  4.7K  [R0402]  95.62 205.55 270 top
R92  4.7K  [R0402]  86.73 205.55 270 top
R93  4.7K  [R0402]  95.62 218.25 270 top
R94  100  [R0402]  116.04 259.21 270 top
R95  130  [R0402]  168.91 230.51 0 top
R96  240  [R0402]  114.81 259.21 270 top
R97  130  [R0402]  153.67 230.51 0 top
R98  300  [R0402]  161.29 230.51 0 top
R99  120  [R0402]  164.85 238.38 0 top
R100  33.2  [R0402]  164.85 237.11 180 top
R101  1K  [R0402]  180.47 230.51 0 top
R102  5.1K  [R0402]  22.99 246.38 180 top
R103  10K  [R0402]  22.99 247.65 0 top
R104  100K  [R0402]  29.21 247.78 180 top
R105  100K  [R0402]  22.99 250.06 0 top
R106  100K  [R0402]  37.08 250.06 180 top
R107  100K  [R0402]  37.08 251.21 180 top
R108  100K  [R0402]  46.1 248.54 180 top
R110  0  [R0201]  61.59 207.01 90 top
R111  0  [R0201]  62.86 207.01 90 top
R112  0  [R0201]  61.59 204.22 270 top
R113  0  [R0201]  62.86 204.22 270 top
R114  0  [R0201]  61.59 202.31 270 top
R115  0  [R0201]  62.86 202.31 270 top
R116  0  [R0201]  61.59 200.41 270 top
R117  0  [R0201]  62.86 200.41 270 top
R118  0  [R0201]  46.74 250.44 180 top
R183  4.7K  [R0402]  171.83 305.18 270 top
R184  4.7K  [R0402]  171.83 303.15 90 top
R185  4.7K  [R0402]  46.74 251.46 0 top
R186  1K  [R0402]  62.61 239.52 180 top
R187  1K  [R0402]  54.61 238.12 270 top
R188  1K  [R0402]  58.67 242.95 0 top
R191  4.7K  [R0402]  55.75 235.59 0 top
R192  4.7K  [R0402]  52.07 235.59 180 top
R193  1K  [R0402]  55.88 238.12 90 top
R195  33.2  [R0402]  63.88 206.88 270 top
R196  33.2  [R0402]  65.15 206.88 270 top
R197  33.2  [R0402]  66.42 206.88 270 top
R198  33.2  [R0402]  67.69 206.88 270 top
R199  33.2  [R0402]  68.96 206.88 270 top
R200  33.2  [R0402]  70.23 206.88 270 top
R201  33.2  [R0402]  71.5 206.88 270 top
R202  100  [R0402]  66.04 221.11 270 bottom
R203  10K  [R0402]  55.24 245.75 90 top
R204  4.7K  [R0402]  65.07 229.29 180 top
R205  4.7K  [R0402]  68.5 229.29 0 top
R206  10K  [R0402]  71.42 225.09 0 top
R207  10K  [R0402]  69.39 225.09 180 top
R208  1K  [R0402]  71.42 223.95 180 top
R209  1K  [R0402]  69.39 223.95 0 top
R210  10K  [R0402]  76.71 216.79 270 bottom
R211  1K  [R0402]  58.93 218.69 0 top
R212  10K  [R0402]  58.55 209.93 90 top
R213  10K  [R0402]  73.66 217.17 0 bottom
R214  10K  [R0402]  73.79 211.58 0 bottom
R215  10K  [R0402]  76.2 211.58 90 bottom
R216  787  [R0402]  32.54 256.77 0 top
R217  787  [R0402]  208.64 234.16 270 top
R218  787  [R0402]  57.94 256.77 0 top
SW1  SPDT PUSHBUTTON  [SW3PSMRA_2SH]  14.61 232.41 90 top
SW2  6PIN,DPDT  [SW_TMD1T5B2M2RE]  48.26 225.68 270 top
SW_BUF_SRC  DPDT  [SW6ST_2P00TH_2MH]  68.45 242.7 90 top
SW_OE0  DPDT  [SW6ST_2P00TH_2MH]  83.55 222.06 270 top
SW_OE1  DPDT  [SW6ST_2P00TH_2MH]  92.44 209.36 270 top
SW_OE2  DPDT  [SW6ST_2P00TH_2MH]  83.55 209.36 270 top
SW_OE3  DPDT  [SW6ST_2P00TH_2MH]  92.44 222.06 270 top
SW_PWR  DPDT  [SW6ST_2P00TH_2MH]  213.36 252.09 180 top
SW_RST  SPDT PUSHBUTTON  [SW3PSMRA_2SH]  14.61 247.65 90 top
TP1  SM TEST PAD,16MIL ROUND  [TP_RD16]  116.97 93.6 0 top
TP2  SM TEST PAD,16MIL ROUND  [TP_RD16]  115.57 96.77 180 bottom
TP3  SM TEST PAD,16MIL ROUND  [TP_RD16]  36.83 92.71 180 bottom
TP4  SM TEST PAD,16MIL ROUND  [TP_RD16]  31.75 101.35 180 bottom
TP5  SM TEST PAD,16MIL ROUND  [TP_RD16]  36.83 95.25 180 bottom
TP6  SM TEST PAD,16MIL ROUND  [TP_RD16]  143.51 91.44 180 top
TP7  SM TEST PAD,16MIL ROUND  [TP_RD16]  31.75 99.06 180 bottom
TP8  SM TEST PAD,16MIL ROUND  [TP_RD16]  34.29 103.5 180 bottom
TP9  SM TEST PAD,16MIL ROUND  [TP_RD16]  34.29 99.06 180 bottom
TP10  SM TEST PAD,16MIL ROUND  [TP_RD16]  36.83 103.5 180 bottom
TP11  SM TEST PAD,16MIL ROUND  [TP_RD16]  31.75 95.25 180 bottom
TP12  SM TEST PAD,16MIL ROUND  [TP_RD16]  34.29 101.35 180 bottom
TP13  SM TEST PAD,16MIL ROUND  [TP_RD16]  90.55 85.85 90 bottom
TP14  SM TEST PAD,16MIL ROUND  [TP_RD16]  34.29 95.25 180 bottom
TP15  SM TEST PAD,16MIL ROUND  [TP_RD16]  36.83 101.35 180 bottom
TP16  SM TEST PAD,16MIL ROUND  [TP_RD16]  31.75 103.5 180 bottom
TP17  SM TEST PAD,16MIL ROUND  [TP_RD16]  36.83 90.17 180 bottom
TP18  SM TEST PAD,16MIL ROUND  [TP_RD16]  36.83 99.06 180 bottom
TP19  SM TEST PAD,16MIL ROUND  [TP_RD16]  38.99 86.49 180 bottom
TP20  SM TEST PAD,16MIL ROUND  [TP_RD16]  37.08 86.49 180 bottom
TP21  SM TEST PAD,16MIL ROUND  [TP_RD16]  35.18 86.49 180 bottom
U1  NC7SZ00  [SOT65P210X110_5N]  22.99 235.59 0 top
U2  NC7SZ00  [SOT65P210X110_5N]  27.69 227.84 0 top
U3  LMC555  [SOIC127P600X175_8N]  18.16 220.22 180 top
U4  NC7SZ00  [SOT65P210X110_5N]  27.69 231.01 0 top
U5  NC7SZ00  [SOT65P210X110_5N]  27.69 239.01 0 top
U6  NC7SZ00  [SOT65P210X110_5N]  22.99 229.24 0 top
U7  NC7SZ00  [SOT65P210X110_5N]  27.69 234.19 0 top
U8  PI3USB102  [QFN40P130X160X80-10N]  106.93 240.41 90 top
U9  LM317L  [SOIC127P600X175_8N]  118.45 254.38 270 top
U10  LM337  [SOT230P700X180_4N]  159.39 240.67 180 top
U11  MAX811  [SOT192P237X122_4N]  26.16 246.76 180 top
U12  MAX811  [SOT192P237X122_4N]  26.16 251.08 0 top
U13  MAX811  [SOT192P237X122_4N]  33.78 247.27 180 top
U14  74LVC1G08  [SOT95P280X145_5N]  33.78 251.21 180 top
U15  MAX811  [SOT192P237X122_4N]  43.05 247.52 180 top
U16  74LVC1G08  [SOT95P280X145_5N]  43.05 251.46 180 top
U17  LP5907  [SOT95P280X145_5N]  62.86 245.49 90 top
U18  SI52202-A01BGM  [QFN40P300X300X90-21]  54.48 241.81 0 top
U19  RC19004AGNL#KB0  [QFN40P400X400X100-29N]  67.82 219.33 270 top
U20  SN74CB3T3125PWR  [SOP65P640X120-14]  74.85 214.3 180 top
U21  NC7SZ14  [SOT65P210X110_5L]  52.58 246.13 0 top
X1  25MHz  [XTAL320X500X110_4N]  48.39 242.32 0 top
X_OSC1  100MHZ  [OSC254P500X700X165_6N]  108.29 255.4 270 top
Z_42.5_TOP  ZSE3PINS2R,IMP COUPON  [ZSE3PINS2R]  71.75 287.15 0 top
Z_42.5_TOP_END  IMP TP SINGLE ENDED  [IMP_TP_1X3_35P]  176.4 288.04 270 top
Z_50_BOT  ZSE3PINS2R,IMP COUPON  [ZSE3PINS2R]  187.2 313.44 0 top
Z_50_BOT_END  IMP TP SINGLE ENDED  [IMP_TP_1X3_35P]  231.39 314.32 270 top
Z_50_TOP  ZSE3PINS2R,IMP COUPON  [ZSE3PINS2R]  187.2 296.16 0 top
Z_50_TOP_END  IMP TP SINGLE ENDED  [IMP_TP_1X3_35P]  231.39 297.05 270 top
Z_85D_BOT  zdi4pins2r  [ZDI4PINS2R]  10.79 295.27 0 top
Z_85D_BOT_END  imp_tp_diff  [IMP_TP_1X4_35P]  62.23 295.34 270 top
Z_85D_TOP  zdi4pins2r  [ZDI4PINS2R]  10.79 314.32 0 top
Z_85D_TOP_END  imp_tp_diff  [IMP_TP_1X4_35P]  62.23 314.39 270 top

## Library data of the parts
C1 C3 = cap: User Part Number: 3MRV8; Tolerance: 20%; tolerance: 20%; signal model: DEFAULT_CAPACITOR_1e+07pF_2_1
C2 C4 C22 C41 C47 C52 C55 C58 = cap: User Part Number: J6201; Tolerance: 10%; tolerance: 10%; signal model: DEFAULT_CAPACITOR_2.2e+06pF_2_1; room: BRD1
C5-C9 C12 C13 C16-C18 C23 C59 C129 = cap: Tolerance: 10%; User Part Number: MNN3J; alternate symbols: ((CAPC0603X33N,C0201M_FOX,C0201_R4)); tolerance: 10%; signal model: DEFAULT_CAPACITOR_100000pF_2_1; room: BRD1
C10 C11 C14 C21 C40 C46 C48 C51 C54 C57 = cap: User Part Number: 3MRV8; Tolerance: 20%; tolerance: 20%; signal model: DEFAULT_CAPACITOR_1e+07pF_2_1; room: BRD1
C15 = cap: User Part Number: RY497; Tolerance: 10%; tolerance: 10%; signal model: DEFAULT_CAPACITOR_1e+06pF_2_1
C19 C20 C38 C39 C44 C45 C49 C50 = cap: User Part Number: C2Y5M; Tolerance: 20%; tolerance: 20%; signal model: DEFAULT_CAPACITOR_4.7e+07pF_2_1
C25 C26 = cap: User Part Number: KN9YT; Tolerance: 10%; tolerance: 10%; signal model: DEFAULT_CAPACITOR_56000pF_2_1; room: BRD1
C36 C37 C42 C43 C60 = cap: User Part Number: 15D2J; Tolerance: 10%; tolerance: 10%; signal model: DEFAULT_CAPACITOR_1e+06pF_2_1
C53 C56 = cap_p: User Part Number: PTT5Y; Tolerance: 20%; tolerance: 20%; signal model: DEFAULT_CAPACITOR_1e+08pF_2_1
C125-C128 = cap: User Part Number: KN9YT; Tolerance: 10%; tolerance: 10%; signal model: DEFAULT_CAPACITOR_56000pF_2_1; room: CAL
C130 C133 C135 C137 C139 C142 C144 C146 C148 C150 C152 C153 = cap: Tolerance: 10%; User Part Number: MNN3J; alternate symbols: ((CAPC0603X33N,C0201M_FOX,C0201_R4)); tolerance: 10%; room: BRD1
C131 C132 C134 C136 C138 C143 C145 C147 C149 C151 = cap: User Part Number: RY497; Tolerance: 10%; tolerance: 10%; room: BRD1
C140 C141 = cap: User Part Number: M5278; Tolerance: 5%; tolerance: 5%; room: BRD1
DS1-DS3 = ps2801: Tolerance: TOL; User Part Number: 3TTYD
DS_3P3V DS_5VSTBY DS_RST DS_TRIG = g_led_a1_c2: Tolerance: TOL; User Part Number: UJ387; room: BRD1
J_S2D_BOT J_S2D_TOP = tp3_pprobeb_sm-empty: User Part Number: 110408130004
L3-L10 = g_ind: Tolerance: TOL; User Part Number: XJ237
LBL1 = 2d_label500x437: User Part Number: HP126; room: BRD1
P1-P4 = g_2x1: User Part Number: RD013; room: BRD1
P6 P7 = g_1x4: User Part Number: Y9609
P8-P10 P_SLEWRATE_SEL = g_2x1: User Part Number: RD013
P_ATX = g_2x12_ss_2mh
P_CAL_CPU_OCP_0_N P_CAL_CPU_OCP_0_P P_OCP_CPU_0_N1 P_OCP_CPU_0_P1 P_OCP_CPU_1_N1 P_OCP_CPU_1_P1 P_OCP_CPU_2_N1 P_OCP_CPU_2_P1 P_OCP_CPU_3_N1 P_OCP_CPU_3_P1 P_OCP_CPU_4_N P_OCP_CPU_4_P4 P_OCP_CPU_5_N P_OCP_CPU_5_P P_OCP_CPU_6_N P_OCP_CPU_6_P P_OCP_CPU_7_N P_OCP_CPU_7_P P_OCP_CPU_8_N P_OCP_CPU_8_P P_OCP_CPU_9_N P_OCP_CPU_9_P P_OCP_CPU_10_N P_OCP_CPU_10_P P_OCP_CPU_11_N P_OCP_CPU_11_P P_OCP_CPU_12_N P_OCP_CPU_12_P P_OCP_CPU_13_N P_OCP_CPU_13_P P_OCP_CPU_14_N P_OCP_CPU_14_P P_OCP_CPU_15_N P_OCP_CPU_15_P P_SMA_BOT_5IN_DN_1 P_SMA_BOT_5IN_DN_2 P_SMA_BOT_5IN_DP_1 P_SMA_BOT_5IN_DP_2 P_SMA_BOT_10IN_DN_1 P_SMA_BOT_10IN_DN_2 P_SMA_BOT_10IN_DP_1 P_SMA_BOT_10IN_DP_2 P_SMA_TOP_5IN_DN_1 P_SMA_TOP_5IN_DN_2 P_SMA_TOP_5IN_DP_1 P_SMA_TOP_5IN_DP_2 P_SMA_TOP_10IN_DN_1 P_SMA_TOP_10IN_DN_2 P_SMA_TOP_10IN_DP_1 P_SMA_TOP_10IN_DP_2 = g_jack_0: alternate symbols: ((96_mmpx-50-0-3_l6_casea))
P_CMTS_N P_CMTS_P P_EXT_CLK_N P_EXT_CLK_P P_NOISEINJ_N P_NOISEINJ_P = g_jack_5p: room: BRD1
P_CPU_OCP_0_N1 P_CPU_OCP_0_P1 P_CPU_OCP_1_N1 P_CPU_OCP_1_P1 P_CPU_OCP_2_N1 P_CPU_OCP_2_P1 P_CPU_OCP_3_N1 P_CPU_OCP_3_P1 P_CPU_OCP_4_N P_CPU_OCP_4_P P_CPU_OCP_5_N P_CPU_OCP_5_P P_CPU_OCP_6_N P_CPU_OCP_6_P P_CPU_OCP_7_N P_CPU_OCP_7_P P_CPU_OCP_8_N P_CPU_OCP_8_P P_CPU_OCP_9_N P_CPU_OCP_9_P P_CPU_OCP_10_N P_CPU_OCP_10_P P_CPU_OCP_11_N P_CPU_OCP_11_P P_CPU_OCP_12_N P_CPU_OCP_12_P P_CPU_OCP_13_N P_CPU_OCP_13_P P_CPU_OCP_14_N P_CPU_OCP_14_P P_CPU_OCP_15_N P_CPU_OCP_15_P = g_jack_1: alternate symbols: ((96_mmpx-50-0-3_l6_casea)); room: BRD1
P_OCP = c84edg_amp
P_OCPEDGE = c84edg_amp: User Part Number: 7HYMF|EDG; alternate symbols: ((CON_AMP_EDGE_ME101681340131X_alt))
Q1 Q2 = ft2n7002k_sot23: User Part Number: FR033; Tolerance: TOL
R1 R3-R5 R9 R10 R12 R13 R17 R21-R23 R26 R27 R37 R101 = res: User Part Number: J5741; Tolerance: 5%; tolerance: 5%; signal model: DEFAULT_RESISTOR_1000.000000OHM_2_1
R2 R6-R8 R11 R14-R16 R18 R110-R118 = res: Tolerance: 5%; User Part Number: YY941; alternate symbols: ((R0201_R4,R0201M_FOX)); tolerance: 5%; signal model: DEFAULT_RESISTOR_0.001OHM_2_1; room: OCPCONN
R19 R25 R29 R31 R35 R36 R38 R39 R43-R45 R47 R53-R56 = res: Tolerance: 5%; User Part Number: YY941; alternate symbols: ((R0201_R4,R0201M_FOX)); tolerance: 5%; signal model: DEFAULT_RESISTOR_0.001OHM_2_1; room: BRD1
R20 R24 R28 R30 R103 = res: User Part Number: N1256; Tolerance: 1%; tolerance: 1%; signal model: DEFAULT_RESISTOR_10000OHM_2_1; room: BRD1
R32 R34 = res: User Part Number: H8992; Tolerance: 1%; tolerance: 1%; signal model: DEFAULT_RESISTOR_24.300000OHM_2_1; room: BRD1
R33 = res: Tolerance: 1%; User Part Number: 3WWMJ; alternate symbols: ((R0201_R4,R0201M_FOX)); tolerance: 1%; signal model: DEFAULT_RESISTOR_1000.000000OHM_2_1; room: BRD1
R48 R49 = res: User Part Number: DP596; Tolerance: 1%; tolerance: 1%; signal model: DEFAULT_RESISTOR_45.300000OHM_2_1
R70 R195-R201 = res: User Part Number: H8997; Tolerance: 1%; tolerance: 1%
R72 R73 R78 R79 R81-R84 = res: User Part Number: J8383; Tolerance: 1%; tolerance: 1%; signal model: DEFAULT_RESISTOR_43.200000OHM_2_1
R86-R93 R185 = res: User Part Number: N5300; Tolerance: 5%; tolerance: 5%; signal model: DEFAULT_RESISTOR_4700OHM_2_1
R94 = res: User Part Number: 33JXG; Tolerance: 1%; tolerance: 1%; signal model: DEFAULT_RESISTOR_100.000000OHM_2_1
R95 R97 = res: User Part Number: J8387; Tolerance: 1%; tolerance: 1%; signal model: DEFAULT_RESISTOR_130.000000OHM_2_1; room: BRD1
R96 = res: User Part Number: P702J; Tolerance: 1%; tolerance: 1%; signal model: DEFAULT_RESISTOR_240.000000OHM_2_1
R98 = res: User Part Number: G3731; Tolerance: 5%; tolerance: 5%; signal model: DEFAULT_RESISTOR_300.000000OHM_2_1
R99 = res: User Part Number: YR3NG; Tolerance: 1%; tolerance: 1%; signal model: DEFAULT_RESISTOR_120.000000OHM_2_1
R100 = res: User Part Number: H8997; Tolerance: 1%; tolerance: 1%; signal model: DEFAULT_RESISTOR_33.200000OHM_2_1
R102 = res: User Part Number: X9651; Tolerance: 1%; tolerance: 1%; signal model: DEFAULT_RESISTOR_5100OHM_2_1
R104-R108 = res: User Part Number: 92259; Tolerance: 5%; tolerance: 5%; signal model: DEFAULT_RESISTOR_100000OHM_2_1
R183 R184 = res: User Part Number: N5300; Tolerance: 5%; tolerance: 5%; signal model: DEFAULT_RESISTOR_4700OHM_2_1; room: CAL
R186-R188 R193 R208 R209 R211 = res: User Part Number: J5741; Tolerance: 5%; tolerance: 5%; room: BRD1
R191 R192 R204 R205 = res: User Part Number: N5300; Tolerance: 5%; tolerance: 5%; room: BRD1
R202 = res: User Part Number: C7553; Tolerance: 5%; tolerance: 5%
R203 R206 R207 R210 = res: User Part Number: N1256; Tolerance: 1%; tolerance: 1%; room: BRD1
R212-R215 = res: User Part Number: N1256; Tolerance: 1%; tolerance: 1%
R216-R218 = res: User Part Number: U024H; Tolerance: 1%; tolerance: 1%
SW1 SW_RST = sw3psmra_spdt: User Part Number: GC8VG; Tolerance: TOL; room: BRD1
SW2 = TMD1T5B2M2RE
SW_BUF_SRC SW_OE0-SW_OE3 SW_PWR = g_2x3_ss: User Part Number: 0C94G; room: BRD1
TP1-TP21 = g_tp: room: BRD1
U1 U2 U4-U7 = g_nand_1slot_a1_b2: Tolerance: TOL; User Part Number: RPWR7; room: BRD1
U3 = lmc555: Tolerance: TOL; User Part Number: 83011; room: BRD1
U8 = pi3usb102-10: User Part Number: GVY50; room: BRD1
U9 = lm317l: Tolerance: TOL; User Part Number: 9F006
U10 = lm337: Tolerance: TOL; User Part Number: 083XW
U11-U13 U15 = max811: Tolerance: TOL; User Part Number: 2E549
U14 U16 = g_and_1slot_a1_b2: Tolerance: TOL; User Part Number: JM641
U17 = lp5907: Tolerance: TOL; User Part Number: TVXF2
U18 = Si52202-A01BGM
U19 = RC19004AGNL-KB0_1
U20 = SN74CB3T3125PWR
U21 = g_inv_1slot_nc1_a2: Tolerance: TOL; User Part Number: DT962
X1 = g_xtal_2x1_4p_24nc: Tolerance: TOL; User Part Number: WW117
X_OSC1 = g_osc_6p: Tolerance: TOL; User Part Number: GDYTG
Z_42.5_TOP Z_50_BOT Z_50_TOP = zse3pins2r: User Part Number: 090730100157; Tolerance: TOL
Z_42.5_TOP_END Z_50_BOT_END Z_50_TOP_END = imp_tp_se: User Part Number: 090730100116
Z_85D_BOT Z_85D_TOP = zdi4pins2r: User Part Number: 00000; Tolerance: TOL
Z_85D_BOT_END Z_85D_TOP_END = imp_tp_diff: User Part Number: 00000

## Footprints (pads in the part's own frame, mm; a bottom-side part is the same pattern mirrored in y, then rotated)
2D_LABEL500X437
  round 0 smd: 1(0,0)
2RAD268D236H098P
  rect 1.346x1.346 hole 0.965: 1(0,0)
  round 1.346 hole 0.965: 2(2.489,0)
96_MMPX-50-0-3_L1_CASEA
  round 0.457 smd: 1(0,0)
  round 1.092 hole 0.813: 2(1.2,-2.15) 3(-2.15,-2.15) 4(-2.15,2.15) 5(1.2,2.15)
  rect 0.051x0.051 smd: 6(-0.457,1.041)
96_MMPX-50-0-3_L1_CASEA#2
  round 0.457 hole 0.203: 1(0,0)
  round 1.092 hole 0.813: 2(1.2,-2.15) 3(-2.15,-2.15) 4(-2.15,2.15) 5(1.2,2.15)
  rect 0.051x0.051 smd: 6(-0.356,0.94)
BERG1X2
  rect 1.575x1.575 hole 1.194: 1(0,0)
  round 1.575 hole 1.194: 2(0,-2.54)
BERG1X4
  rect 1.575x1.575 hole 1.194: 1(0,0)
  round 1.575 hole 1.194: 2(0,-2.54) 3(0,-5.08) 4(0,-7.62)
C2X84STF_MCE_0P60_5MH_2PG
  oval 1.61x2.96 hole 1.1x2.45: (-1.55,1.75) (11.86,1.75) (32.23,1.75) (44.49,1.75) (66.52,1.75)
  round 0 hole 1.1 unplated: (0,0) (64.97,1.75)
  custom 0.087x0.087 smd: A1(14.015,4.05) A2(14.615,4.05) A3(15.215,4.05) A4(15.815,4.05) A5(16.415,4.05) A6(17.015,4.05) A7(17.615,4.05) A8(18.215,4.05) A9(18.815,4.05) A10(19.415,4.05) A11(20.015,4.05) A12(20.615,4.05) A13(21.215,4.05) A14(21.815,4.05) A15(22.415,4.05) A16(23.015,4.05) A17(23.615,4.05) A18(24.215,4.05) A19(24.815,4.05) A20(25.415,4.05) A21(26.015,4.05) A22(26.615,4.05) A23(27.215,4.05) A24(27.815,4.05) A25(28.415,4.05) A26(29.015,4.05) A27(29.615,4.05) A28(30.215,4.05) A29(34.225,4.05) A30(34.825,4.05) A31(35.425,4.05) A32(36.025,4.05) A33(36.625,4.05) A34(37.225,4.05) A35(37.825,4.05) A36(38.425,4.05) A37(39.025,4.05) A38(39.625,4.05) A39(40.225,4.05) A40(40.825,4.05) A41(41.425,4.05) A42(42.025,4.05) A43(46.935,4.05) A44(47.535,4.05) A45(48.135,4.05) A46(48.735,4.05) A47(49.335,4.05) A48(49.935,4.05) A49(50.535,4.05) A50(51.135,4.05) A51(51.735,4.05) A52(52.335,4.05) A53(52.935,4.05) A54(53.535,4.05) A55(54.135,4.05) A56(54.735,4.05) A57(55.335,4.05) A58(55.935,4.05) A59(56.535,4.05) A60(57.135,4.05) A61(57.735,4.05) A62(58.335,4.05) A63(58.935,4.05) A64(59.535,4.05) A65(60.135,4.05) A66(60.735,4.05) A67(61.335,4.05) A68(61.935,4.05) A69(62.535,4.05) A70(63.135,4.05) B1(14.015,-0.55) B2(14.615,-0.55) B3(15.215,-0.55) B4(15.815,-0.55) B5(16.415,-0.55) B6(17.015,-0.55) B7(17.615,-0.55) B8(18.215,-0.55) B9(18.815,-0.55) B10(19.415,-0.55) B11(20.015,-0.55) B12(20.615,-0.55) B13(21.215,-0.55) B14(21.815,-0.55) B15(22.415,-0.55) B16(23.015,-0.55) B17(23.615,-0.55) B18(24.215,-0.55) B19(24.815,-0.55) B20(25.415,-0.55) B21(26.015,-0.55) B22(26.615,-0.55) B23(27.215,-0.55) B24(27.815,-0.55) B25(28.415,-0.55) B26(29.015,-0.55) B27(29.615,-0.55) B28(30.215,-0.55) B29(34.225,-0.55) B30(34.825,-0.55) B31(35.425,-0.55) B32(36.025,-0.55) B33(36.625,-0.55) B34(37.225,-0.55) B35(37.825,-0.55) B36(38.425,-0.55) B37(39.025,-0.55) B38(39.625,-0.55) B39(40.225,-0.55) B40(40.825,-0.55) B41(41.425,-0.55) B42(42.025,-0.55) B43(46.935,-0.55) B44(47.535,-0.55) B45(48.135,-0.55) B46(48.735,-0.55) B47(49.335,-0.55) B48(49.935,-0.55) B49(50.535,-0.55) B50(51.135,-0.55) B51(51.735,-0.55) B52(52.335,-0.55) B53(52.935,-0.55) B54(53.535,-0.55) B55(54.135,-0.55) B56(54.735,-0.55) B57(55.335,-0.55) B58(55.935,-0.55) B59(56.535,-0.55) B60(57.135,-0.55) B61(57.735,-0.55) B62(58.335,-0.55) B63(58.935,-0.55) B64(59.535,-0.55) B65(60.135,-0.55) B66(60.735,-0.55) B67(61.335,-0.55) B68(61.935,-0.55) B69(62.535,-0.55) B70(63.135,-0.55) OCP_A1(1.82,4.05) OCP_A2(2.42,4.05) OCP_A3(3.02,4.05) OCP_A4(3.62,4.05) OCP_A5(4.22,4.05) OCP_A6(4.82,4.05) OCP_A7(5.42,4.05) OCP_A8(6.02,4.05) OCP_A9(6.62,4.05) OCP_A10(7.22,4.05) OCP_A11(7.82,4.05) OCP_A12(8.42,4.05) OCP_A13(9.02,4.05) OCP_A14(9.62,4.05) OCP_B1(1.82,-0.55) OCP_B2(2.42,-0.55) OCP_B3(3.02,-0.55) OCP_B4(3.62,-0.55) OCP_B5(4.22,-0.55) OCP_B6(4.82,-0.55) OCP_B7(5.42,-0.55) OCP_B8(6.02,-0.55) OCP_B9(6.62,-0.55) OCP_B10(7.22,-0.55) OCP_B11(7.82,-0.55) OCP_B12(8.42,-0.55) OCP_B13(9.02,-0.55) OCP_B14(9.62,-0.55)
C0201
  custom 0.075x0.075 smd: 1(-0.25,0) 2(0.25,0)
C0402
  rect 0.508x0.508 smd: 1(-0.432,0) 2(0.432,0)
C0603
  rect 0.762x0.762 smd: 1(-0.711,0) 2(0.711,0)
C1206
  oval 1.016x1.778 smd: 1(-1.524,0) 2(1.524,0)
CON_AMP_EDGE_ME101681340131X
  rect 0.38x2.12 smd: A1(49.12,0) A4(47.32,0) A7(45.52,0) A10(43.72,0) A13(41.92,0) A16(40.12,0) A19(38.32,0) A22(36.52,0) A25(34.72,0) A28(32.92,0) A29(28.91,0) A32(27.11,0) A35(25.31,0) A38(23.51,0) A41(21.71,0) A43(16.2,0) A46(14.4,0) A49(12.6,0) A52(10.8,0) A55(9,0) A58(7.2,0) A61(5.4,0) A64(3.6,0) A67(1.8,0) A70(0,0) B1(49.12,0) B4(47.32,0) B7(45.52,0) B10(43.72,0) B13(41.92,0) B16(40.12,0) B19(38.32,0) B22(36.52,0) B25(34.72,0) B28(32.92,0) B29(28.91,0) B32(27.11,0) B35(25.31,0) B38(23.51,0) B41(21.71,0) B43(16.2,0) B46(14.4,0) B49(12.6,0) B52(10.8,0) B55(9,0) B58(7.2,0) B61(5.4,0) B64(3.6,0) B67(1.8,0) B70(0,0) OCP_A1(61.315,0) OCP_A4(59.515,0) OCP_A7(57.715,0) OCP_A10(55.915,0) OCP_A13(54.115,0) OCP_B1(61.315,0) OCP_B4(59.515,0) OCP_B7(57.715,0) OCP_B10(55.915,0) OCP_B13(54.115,0)
  rect 0.38x1.72 smd: A2(48.52,-0.2) A3(47.92,-0.2) A5(46.72,-0.2) A6(46.12,-0.2) A8(44.92,-0.2) A9(44.32,-0.2) A11(43.12,-0.2) A12(42.52,-0.2) A14(41.32,-0.2) A15(40.72,-0.2) A17(39.52,-0.2) A18(38.92,-0.2) A20(37.72,-0.2) A21(37.12,-0.2) A23(35.92,-0.2) A24(35.32,-0.2) A26(34.12,-0.2) A27(33.52,-0.2) A30(28.31,-0.2) A31(27.71,-0.2) A33(26.51,-0.2) A34(25.91,-0.2) A36(24.71,-0.2) A37(24.11,-0.2) A39(22.91,-0.2) A40(22.31,-0.2) A42(21.11,-0.2) A44(15.6,-0.2) A45(15,-0.2) A47(13.8,-0.2) A48(13.2,-0.2) A50(12,-0.2) A51(11.4,-0.2) A53(10.2,-0.2) A54(9.6,-0.2) A56(8.4,-0.2) A57(7.8,-0.2) A59(6.6,-0.2) A60(6,-0.2) A62(4.8,-0.2) A63(4.2,-0.2) A65(3,-0.2) A66(2.4,-0.2) A68(1.2,-0.2) A69(0.6,-0.2) B2(48.52,-0.201) B3(47.92,-0.201) B5(46.72,-0.201) B6(46.12,-0.201) B8(44.92,-0.201) B9(44.32,-0.201) B11(43.12,-0.201) B12(42.52,-0.201) B14(41.32,-0.201) B15(40.72,-0.201) B17(39.52,-0.201) B18(38.92,-0.201) B20(37.72,-0.201) B21(37.12,-0.201) B23(35.92,-0.201) B24(35.32,-0.201) B26(34.12,-0.201) B27(33.52,-0.201) B30(28.31,-0.201) B31(27.71,-0.201) B33(26.51,-0.201) B34(25.91,-0.201) B36(24.71,-0.201) B37(24.11,-0.201) B39(22.91,-0.201) B40(22.31,-0.201) B42(21.11,-0.201) B44(15.6,-0.201) B45(15,-0.201) B47(13.8,-0.201) B48(13.2,-0.201) B50(12,-0.201) B51(11.4,-0.201) B53(10.2,-0.201) B54(9.6,-0.201) B56(8.4,-0.201) B57(7.8,-0.201) B59(6.6,-0.201) B60(6,-0.201) B62(4.8,-0.201) B63(4.2,-0.201) B65(3,-0.201) B66(2.4,-0.201) B68(1.2,-0.201) B69(0.6,-0.201) OCP_A2(60.715,-0.2) OCP_A3(60.115,-0.2) OCP_A5(58.915,-0.2) OCP_A6(58.315,-0.2) OCP_A8(57.115,-0.2) OCP_A9(56.515,-0.2) OCP_A11(55.315,-0.2) OCP_A12(54.715,-0.2) OCP_A14(53.515,-0.2) OCP_B2(60.715,-0.201) OCP_B3(60.115,-0.201) OCP_B5(58.915,-0.201) OCP_B6(58.315,-0.201) OCP_B8(57.115,-0.201) OCP_B9(56.515,-0.201) OCP_B11(55.315,-0.201) OCP_B12(54.715,-0.201) OCP_B14(53.515,-0.201)
CON_HDR_2X12_ST_TH_PWR
  round 2.997 hole 2.997 unplated: (-4.7,-5.04) (50.901,-5.04)
  rect 1.778x1.778 hole 1.397: 1(0,0)
  round 1.778 hole 1.397: 2(4.2,0) 3(8.4,0) 4(12.6,0) 5(16.8,0) 6(21,0) 7(25.2,0) 8(29.4,0) 9(33.6,0) 10(37.8,0) 11(42,0) 12(46.2,0) 13(0,-5.5) 14(4.2,-5.5) 15(8.4,-5.5) 16(12.6,-5.5) 17(16.8,-5.5) 18(21,-5.5) 19(25.2,-5.5) 20(29.4,-5.5) 21(33.6,-5.5) 22(37.8,-5.5) 23(42,-5.5) 24(46.2,-5.5)
CON_SMP_PLUG_STF
  oval 0.406x1.194 smd: 1(0,3.1)
  round 1.6 hole 1.194: MH1(-2.54,2.54) MH2(2.54,2.54) MH3(-2.54,-2.54) MH4(2.54,-2.54)
FB1005X55N
  rect 0.6x0.6 smd: 1(-0.45,0) 2(0.45,0)
IMP_TP_1X3_35P
  round 0.635 hole 0.305: 1(0,0) 2(0.889,0) 3(1.778,0)
IMP_TP_1X4_35P
  round 0.635 hole 0.305: 1(0,0) 2(0.889,0) 3(1.778,0) 4(2.667,0)
LEDC1608X65N
  rect 0.8x0.95 smd: 1(-0.8,0) 2(0.8,0)
OSC254P500X700X165_6N
  rect 1.9x1.55 smd: 1(-2.1,2.54) 2(-2.1,0) 3(-2.1,-2.54) 4(2.1,-2.54) 5(2.1,0) 6(2.1,2.54)
QFN40P130X160X80-10N
  oval 0.95x0.2 smd: 1(-0.575,0.2)
  oval 0.9x0.2 smd: 2(-0.6,-0.2) 6(0.6,-0.2) 7(0.6,0.2)
  oval 0.2x0.7 smd: 3(-0.4,-0.85) 4(0,-0.85) 5(0.4,-0.85) 8(0.4,0.85) 9(0,0.85) 10(-0.4,0.85)
QFN40P300X300X90-21
  rrect 0.7x0.2 smd: 1(-1.55,0.8) 2(-1.55,0.4) 3(-1.55,0) 4(-1.55,-0.4) 5(-1.55,-0.8) 11(1.55,-0.8) 12(1.55,-0.4) 13(1.55,0) 14(1.55,0.4) 15(1.55,0.8)
  rrect 0.2x0.7 smd: 6(-0.8,-1.55) 7(-0.4,-1.55) 8(0,-1.55) 9(0.4,-1.55) 10(0.8,-1.55) 16(0.8,1.55) 17(0.4,1.55) 18(0,1.55) 19(-0.4,1.55) 20(-0.8,1.55)
  rrect 1.9x1.9 smd: 21(0,0)
QFN40P400X400X100-29N
  rrect 0.55x0.2 smd: 1(-1.875,1.2) 2(-1.875,0.8) 3(-1.875,0.4) 4(-1.875,0) 5(-1.875,-0.4) 6(-1.875,-0.8) 7(-1.875,-1.2) 15(1.875,-1.2) 16(1.875,-0.8) 17(1.875,-0.4) 18(1.875,0) 19(1.875,0.4) 20(1.875,0.8) 21(1.875,1.2)
  rrect 0.2x0.55 smd: 8(-1.2,-1.875) 9(-0.8,-1.875) 10(-0.4,-1.875) 11(0,-1.875) 12(0.4,-1.875) 13(0.8,-1.875) 14(1.2,-1.875) 22(1.2,1.875) 23(0.8,1.875) 24(0.4,1.875) 25(0,1.875) 26(-0.4,1.875) 27(-0.8,1.875) 28(-1.2,1.875)
  rrect 2.6x2.6 smd: 29(0,0)
R0201
  custom 0.075x0.075 smd: 1(-0.25,0) 2(0.25,0)
R0402
  rect 0.508x0.508 smd: 1(-0.432,0) 2(0.432,0)
SOIC127P600X175_8N
  oval 2x0.6 smd: 1(-2.45,1.905) 2(-2.45,0.635) 3(-2.45,-0.635) 4(-2.45,-1.905) 5(2.45,-1.905) 6(2.45,-0.635) 7(2.45,0.635) 8(2.45,1.905)
SOIC127P700X230_4N
  oval 1.6x0.6 smd: 1(-3.2,0.635) 2(-3.2,-0.635) 3(3.2,-0.635) 4(3.2,0.635)
SOP65P640X120-14
  rrect 0.35x1.6 smd: 1(-1.95,-2.8) 2(-1.3,-2.8) 3(-0.65,-2.8) 4(0,-2.8) 5(0.65,-2.8) 6(1.3,-2.8) 7(1.95,-2.8) 8(1.95,2.8) 9(1.3,2.8) 10(0.65,2.8) 11(0,2.8) 12(-0.65,2.8) 13(-1.3,2.8) 14(-1.95,2.8)
SOT65P210X110_5L
  oval 0.7x0.4 smd: 1(-0.9,0.65) 2(-0.9,0) 3(-0.9,-0.65) 4(0.9,-0.65) 5(0.9,0.65)
SOT65P210X110_5N
  oval 1.2x0.4 smd: 1(-0.95,0.65) 2(-0.95,0) 3(-0.95,-0.65) 4(0.95,-0.65) 5(0.95,0.65)
SOT95P237X117_3N
  oval 1.3x0.6 smd: 1(-1.05,0.95) 2(-1.05,-0.95) 3(1.05,0)
SOT95P280X145_5N
  oval 1.2x0.6 smd: 1(-1.25,0.95) 2(-1.25,0) 3(-1.25,-0.95) 4(1.25,-0.95) 5(1.25,0.95)
SOT192P237X122_4N
  rect 1.3x1.05 smd: 1(-1.05,0.76)
  rect 1.3x0.6 smd: 2(-1.05,-0.96) 3(1.05,-0.96) 4(1.05,0.96)
SOT230P700X180_4N
  rect 2.1x0.95 smd: 1(-2.95,2.3) 2(-2.95,0) 3(-2.95,-2.3)
  rect 2.1x3.2 smd: 4(2.95,0)
SW3PSMRA_2SH
  custom 0.813x0.813 smd: (-1.778,4.534) (1.778,4.534)
  rect 3.81x2.032 smd: 1(-3.683,-4.534) 3(3.683,-4.534)
  rect 1.016x2.286 smd: 2(0,-4.534)
SW6ST_2P00TH_2MH
  round 1.194 hole 1.194 unplated: (-2.8,-1) (6.8,-1)
  round 1.168 hole 0.787: 1(0,0) 2(2,0) 3(4,0) 4(0,-2) 5(2,-2) 6(4,-2)
SW_TMD1T5B2M2RE
  round 1.44 hole 1.09: 1(0,0) 2(0,2.54) 3(0,5.08) 4(5.08,0) 5(5.08,2.54) 6(5.08,5.08)
TP3_PPROBEB
  round 0.254 hole 1.27 unplated: (-1.397,2.286) (-1.397,-2.286) (2.667,2.286) (2.667,-2.286)
  custom 0.267x0.267 hole 0.254: 1(0,0)
  rect 0.305x0.203 smd: 2(0.635,-0.225) 3(0.635,0.225)
TP_RD16
  round 0.406 smd: TEST(0,0)
unnamed
  round 3.175 hole 3.175 unplated: (0,0)
unnamed#3
  round 1.067 hole 1.067 unplated: (-1.905,0) (1.905,0)
  round 0.711 hole 0.711 unplated: (-0.635,0) (0.635,0)
XTAL320X500X110_4N
  rect 1.2x1.55 smd: 1(-1.1,1.825) 2(-1.1,-1.825) 3(1.1,-1.825) 4(1.1,1.825)
ZDI4PINS2R
  round 1.092 hole 0.711: 1(0,0) 2(2.54,0) 3(0,-2.54) 4(2.54,-2.54)
ZSE3PINS2R
  round 1.092 hole 0.711: 1(0,0) 2(2.54,0) 3(0,-2.54)

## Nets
